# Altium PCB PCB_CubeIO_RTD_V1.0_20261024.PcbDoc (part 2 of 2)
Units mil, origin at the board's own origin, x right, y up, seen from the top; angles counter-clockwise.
Board outline 9739 x 8533 mil, 4 copper layers (TopLayer, GND, VCC, BottomLayer); 78 components, 50 nets, 272 pads, 89 vias.
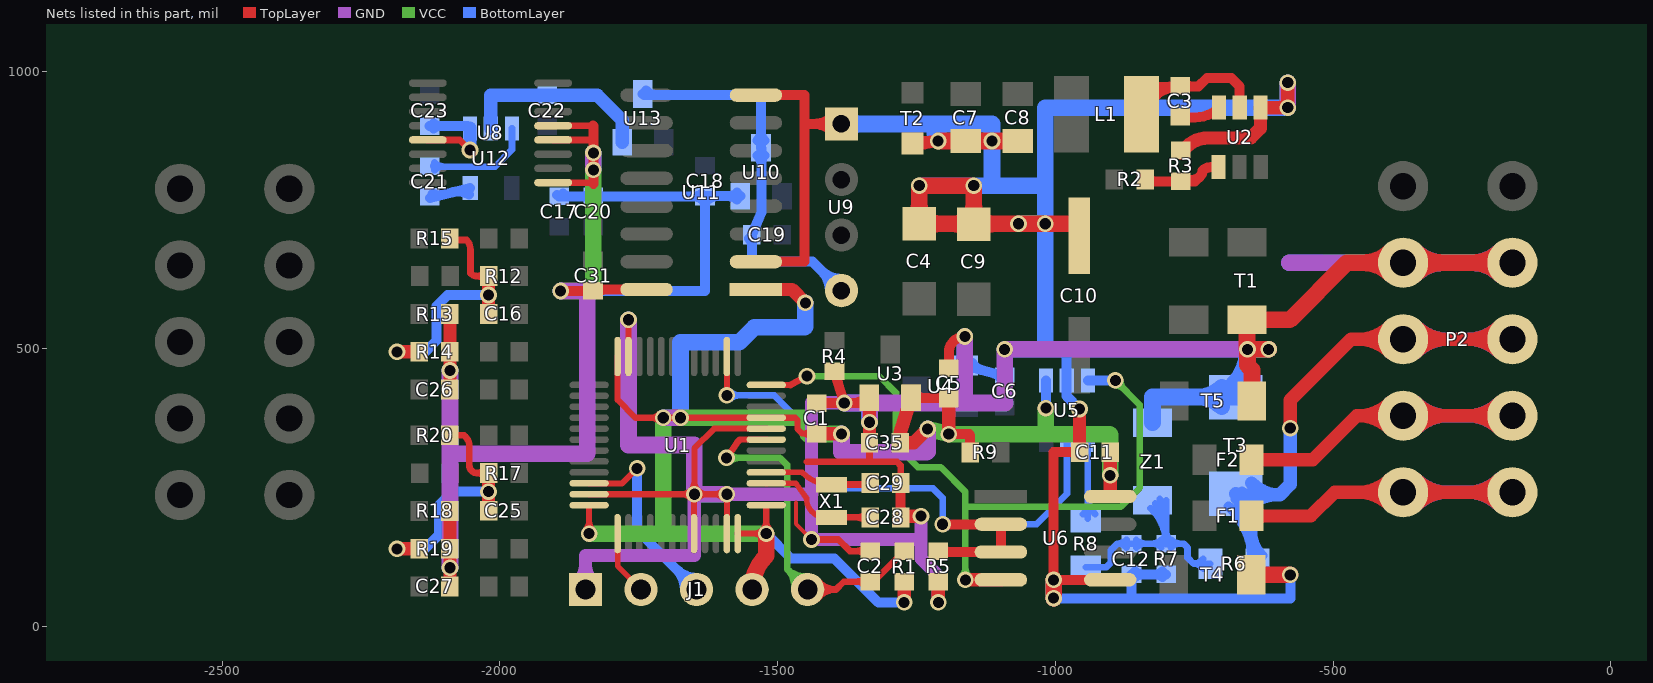
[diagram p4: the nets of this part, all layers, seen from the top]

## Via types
v1: diameter 30, hole 20, TopLayer to BottomLayer, 87 vias
v2: diameter 24, hole 12, TopLayer to BottomLayer, 2 vias

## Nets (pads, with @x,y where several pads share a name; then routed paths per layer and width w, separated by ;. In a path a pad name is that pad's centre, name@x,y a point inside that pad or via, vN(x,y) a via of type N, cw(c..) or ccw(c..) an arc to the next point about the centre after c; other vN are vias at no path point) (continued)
CPU_TXD: U1.12 U5.3 U6.4 | length 1451.7
  TopLayer w11: U1.12@-1520.51,435.14 -1476.96,435.14
  TopLayer w12: -1476.96,435.14 v1(-1446.96,450.87)
  TopLayer w24: v1(-1161.96,84.27) U6.4@-1097.96,84.27
  VCC w12: v1(-1446.96,450.87) -1316.96,450.87 -1286.96,420.87 -1286.96,326.68 -1247.16,286.87 -1206.16,286.87 -1161.96,242.68 -1161.96,215.87 ; v1(-1161.96,84.27) -1161.96,215.87 ; v1(-891.96,443.27) -847.96,399.27 -847.96,249.87 -881.96,215.87 -1161.96,215.87 ; -1161.96,106 cw(c-1183.69,106) -1168.32,90.64 ccw(c-1183.69,106) -1161.96,106 ; -1161.96,106 ccw(c-1140.23,106) -1155.6,90.64 cw(c-1140.23,106) -1161.96,106 ; -876.6,427.91 cw(c-861.23,443.27) -882.96,443.27 ccw(c-861.23,443.27) -876.6,427.91 ; -876.6,427.91 ccw(c-891.96,412.55) -891.96,434.27 cw(c-891.96,412.55) -876.6,427.91
  BottomLayer w18: U5.3@-941.16,443.27 v1(-891.96,443.27)
CPU_TXDEN: R5.2 U1.14 U5.5 U6.2 U6.3 | length 1412.1
  TopLayer w11: v1(-1591.38,416.46) U1.14@-1591.38,486.32
  TopLayer w18: R5.2@-1210.67,134.27 U6.3@-1097.96,134.27 U6.2@-1097.96,184.27 v1(-1202.96,184.27) ; R5.2@-1203.93,140.66 ccw(c-1188.5,156.09) -1188.5,134.27 cw(c-1188.5,156.09) R5.2@-1203.93,140.66
  BottomLayer w12: v1(-1591.38,416.46) -1506.54,416.46 -1444.96,354.87 -1444.96,273.87 -1419.96,248.87 -1219.96,248.87 -1202.96,231.87 v1(-1202.96,184.27) -1033.96,184.27 -978.96,239.27 U5.5@-978.96,336.27 ; -1569.65,416.46 cw(c-1569.65,438.18) -1585.01,422.82 ccw(c-1569.65,438.18) -1569.65,416.46 ; -1569.65,416.46 ccw(c-1569.65,394.73) -1585.01,410.09 cw(c-1569.65,394.73) -1569.65,416.46 ; -1181.23,184.27 cw(c-1181.23,206) -1196.6,190.64 ccw(c-1181.23,206) -1181.23,184.27 ; -1181.23,184.27 ccw(c-1181.23,162.55) -1196.6,177.91 cw(c-1181.23,162.55) -1181.23,184.27
DVDD: C1.1 C5.1 C11.2 C35.1 J1.4 R1.2 R9.2 U1.1 U1.9 U1.24 U1.36 U1.48 U3.2 U5.1 U6.8 U11.1 | length 4234.6
  TopLayer w11: v1(-1839.41,167.42) U1.36@-1839.41,218.6 ; U1.24@-1788.23,486.32 -1788.23,408.14 -1756.17,376.09 U1.9@-1520.51,376.09 -1468.17,376.09 -1463.96,371.87 -1463.96,355.75 -1455.58,347.38 ; U1.48@-1571.69,167.42 v1(-1520.51,167.42) ; v1@-1520.51,169.97 U1.1@-1520.51,218.6 ; C1.1@-1429.67,347.38 -1455.58,347.38 ; -1839.41,190.36 cw(c-1862.34,190.36) -1846.13,174.14 ccw(c-1862.34,190.36) -1839.41,190.36 ; -1839.41,190.36 ccw(c-1816.47,190.36) -1832.69,174.14 cw(c-1816.47,190.36) -1839.41,190.36 ; -1728.89,376.08 cw(c-1728.89,353.15) -1712.68,369.37 ccw(c-1728.89,353.15) -1728.89,376.08 ; -1728.89,376.09 ccw(c-1728.89,399.02) -1712.68,382.8 cw(c-1728.89,399.02) -1728.89,376.09 ; -1543.45,167.42 cw(c-1543.45,144.49) -1527.23,160.71 ccw(c-1543.45,144.49) -1543.45,167.42 ; -1543.45,167.42 ccw(c-1543.45,190.36) v1@-1527.23,174.14 ; -1543.45,167.42 ccw(c-1543.45,190.36) v1@-1527.23,174.14 ; v1@-1527.23,174.14 ccw(c-1543.45,190.36) -1520.51,190.36 ; v1@-1527.23,174.14 ccw(c-1543.45,190.36) -1520.51,190.36 ; -1520.51,190.36 ccw(c-1497.58,190.36) -1513.79,174.14 cw(c-1497.58,190.36) -1520.51,190.36 ; -1455.58,347.38 cw(c-1455.58,324.53) -1439.06,340.3 ccw(c-1455.58,324.53) -1455.58,347.38 ; -1455.58,347.38 ccw(c-1455.58,370.22) -1439.06,354.45 cw(c-1455.58,370.22) -1455.58,347.38
  TopLayer w18: U3.2@-1259.96,411.87 C5.1@-1198.77,411.87 ; v1(-1191.96,346.56) -1154.96,346.56 -1153.58,345.18 R9.2@-1153.58,313.56 ; U6.8@-901.34,234.51 U6.8@-901.11,234.27 ; -1238.92,411.87 cw(c-1238.92,432.92) -1253.8,418.04 ccw(c-1238.92,432.92) -1238.92,411.87 ; -1238.92,411.87 ccw(c-1238.92,390.83) -1253.8,405.71 cw(c-1238.92,390.83) -1238.92,411.87 ; -1153.58,331.82 cw(c-1169.86,331.82) -1158.35,320.3 ccw(c-1169.86,331.82) -1153.58,331.82 ; -1153.58,331.83 ccw(c-1137.28,331.83) -1148.8,320.3 cw(c-1137.28,331.83) -1153.58,331.83 ; -1213.59,411.87 cw(c-1213.59,390.41) -1198.41,405.59 ccw(c-1213.59,390.41) -1213.59,411.87
  TopLayer w24: U11.1@-1539,607 -1474,607 v1(-1450,583) ; C1.1@-1429.67,347.38 v1@-1385.46,347.38 ; C35.1@-1279.46,331.16 -1254.67,331.16 v1(-1229.96,355.87) ; C35.1@-1279.46,348.16 U3.2@-1259.96,411.87 ; v1(-1272.25,43.56) R1.2@-1272.25,80.66 ; v1(-1191.96,346.56) C5.1@-1191.96,410.85 ; U6.8@-901.34,234.51 C11.2@-901.34,313.98 ; U3.2@-1266.87,389.29 cw(c-1248.03,383.52) -1257.28,400.92 ccw(c-1248.03,383.52) U3.2@-1266.87,389.29
  TopLayer w30: J1.4@-1545.96,66.87 cw(c-1461.46,66.87) -1521.21,126.62 -1520.51,127.32 v1(-1520.51,167.42)
  GND w30: v1(-1705.96,376.09) v1(-1674.96,376.09) ; v1(-1384.96,346.87) -1384.96,313.87 -1231.27,313.87 -1229.96,315.18 v1(-1229.96,355.87)
  VCC w24: -902.25,346.56 -901.34,345.66
  VCC w30: v1(-1839.41,167.42) v1(-1520.51,167.42) ; -1705.96,168.42 v1(-1705.96,376.09) v1(-1674.96,376.09) -1445.96,376.09 -1445.96,347.38 -1445.96,346.87 v1(-1384.96,346.87) ; v1(-1229.96,355.87) v1(-1191.96,346.56) -902.25,346.56 ; -1016.96,351.56 v1(-1016.96,393.27) ; v1(-901.34,272.27) -901.34,345.66
  BottomLayer w18: v1(-1520.51,167.42) -1475.96,122.87 -1397.96,122.87 -1318.65,43.56 v1(-1272.25,43.56) ; v1(-1016.96,393.27) U5.1@-1016.96,443.27
  BottomLayer w30: v1(-1705.96,376.09) v1(-1674.96,376.09) -1674.96,512 -1569,512 -1542,539 -1451,539 -1450,540 v1(-1450,583)
GNDX: C1.2 C2.2 C4.2 C5.2 C6.2 C7.2 C8.2 C9.2 C10.2 C11.1 C12.2 C28.1 C29.1 C35.2 J1.1 P2.2 R3.1 R4.1 R5.1 R7.1 T1.2 T2.2 T3.2 T4.2 T5.2 U1.8 U1.23 U1.35 U1.44 U1.47 U2.4 U3.1 U4.1 U5.2 U6.5 U9.1 U11.2 U11.8 Z1.1 | length 15631
  TopLayer w8: -1466.96,222.87 -1466.96,184.87 v1(-1438.96,156.87)
  TopLayer w11: U1.35@-1839.41,238.29 -1591.79,238.29 v1@-1591.38,237.87 ; U1.23@-1768.54,486.32 v1(-1768.54,552.46) ; U1.44@-1650.43,167.42 v1@-1650.43,238.29 ; v1(-1649.96,238.29) -1649.96,320.87 -1614.43,356.4 U1.8@-1520.51,356.4 ; U1.47@-1591.38,167.42 v1(-1591.38,238.29) ; -1672.89,238.29 cw(c-1672.89,215.35) -1656.68,231.57 ccw(c-1672.89,215.35) -1672.89,238.29 ; -1672.89,238.29 ccw(c-1672.89,261.22) v1@-1656.68,245.01 ; -1672.89,238.29 ccw(c-1672.89,261.22) v1@-1656.68,245.01 ; v1@-1656.68,245.01 ccw(c-1672.89,261.22) -1649.96,261.22 ; v1@-1656.68,245.01 ccw(c-1672.89,261.22) -1649.96,261.22 ; -1649.96,261.22 ccw(c-1627.02,261.22) v1@-1643.24,245.01 ; -1649.96,261.22 ccw(c-1627.02,261.22) v1@-1643.24,245.01 ; v1@-1643.24,245.01 ccw(c-1627.02,261.22) -1627.02,238.29 ; v1@-1643.24,245.01 ccw(c-1627.02,261.22) -1627.02,238.29 ; -1627.02,238.29 ccw(c-1627.02,215.35) -1643.24,231.57 cw(c-1627.02,215.35) -1627.02,238.29 ; -1614.31,238.29 cw(c-1614.31,215.35) -1598.09,231.57 ccw(c-1614.31,215.35) -1614.31,238.29 ; -1614.31,238.29 ccw(c-1614.31,261.22) -1598.09,245.01 cw(c-1614.31,261.22) -1614.31,238.29
  TopLayer w12: -1446.96,296.87 -1284.96,296.87 -1278.46,290.38 C29.1@-1278.46,258.56 ; v1(-1438.96,156.87) -1390.96,156.87 -1369.98,135.9 C2.2@-1333.09,135.9 ccw(c-1333.09,136.99) C2.2@-1332,136.99 ; -1334.58,297.26 C35.2@-1334.58,331.16 ; -1358.59,135.9 cw(c-1358.59,112.36) -1341.95,129 ccw(c-1358.59,112.36) -1358.59,135.9 ; -1358.59,135.9 ccw(c-1358.59,159.43) -1341.95,142.79 cw(c-1358.59,159.43) -1358.59,135.9
  TopLayer w18: U11.2@-1539,657 -1452,657 -1452,957 U11.8@-1539,957 ; -1452,905 U9.1@-1385,905 ; C1.2@-1429.67,402.49 U3.1@-1334.58,402.49 ; R4.1@-1397.67,459.38 v1(-1379.96,402.49) ; C28.1@-1278.46,190.52 C28.1@-1278.46,196.56 -1278.46,228.87 C29.1@-1278.46,258.56 ; C5.2@-1191.67,465.47 -1191.67,493.56 ; C11.1@-956.46,313.98 -1003.25,313.98 -1003.25,85.56 -1001.96,84.27 -977.96,84.27 U6.5@-901.11,84.27 ; -1435.7,905 cw(c-1435.7,854.3) -1399.85,890.15 ccw(c-1435.7,854.3) -1435.7,905 ; -1435.7,905 ccw(c-1435.7,955.7) -1399.85,919.85 cw(c-1435.7,955.7) -1435.7,905 ; -1411.41,402.49 cw(c-1411.41,418.78) -1422.93,407.26 ccw(c-1411.41,418.78) -1411.41,402.49 ; -1411.41,402.49 ccw(c-1411.41,386.2) -1422.93,397.72 cw(c-1411.41,386.2) -1411.41,402.49 ; -1278.46,214.83 cw(c-1294.76,214.83) -1283.24,203.3 ccw(c-1294.76,214.83) -1278.46,214.83 ; -1278.46,214.82 ccw(c-1262.18,214.82) -1273.69,203.3 cw(c-1262.18,214.82) -1278.46,214.82 ; -1191.67,481.76 cw(c-1207.96,481.76) -1196.44,470.24 ccw(c-1207.96,481.76) -1191.67,481.76 ; -1191.67,481.76 ccw(c-1175.38,481.76) -1186.9,470.24 cw(c-1175.38,481.76) -1191.67,481.76 ; -1191.67,493.56 cw(c-1162.96,493.56) v1(-1162.96,522.27) ; -1191.67,493.56 cw(c-1162.96,493.56) v1(-1162.96,522.27) ; -1191.67,493.56 cw(c-1162.96,493.56) v1(-1162.96,522.27) ; -972.75,313.98 cw(c-972.75,297.69) -961.23,309.21 ccw(c-972.75,297.69) -972.75,313.98 ; -972.75,313.98 ccw(c-972.75,330.28) -961.23,318.76 cw(c-972.75,330.28) -972.75,313.98 ; -1391.31,438.94 cw(c-1369.63,445.68) -1389.73,456.24 ccw(c-1369.63,445.68) -1391.31,438.94 ; -1364.4,402.49 ccw(c-1364.4,435.41) -1341.12,412.13 cw(c-1364.4,435.41) -1364.4,402.49 ; C29.1@-1283.24,251.82 cw(c-1294.76,240.3) -1278.46,240.3 ccw(c-1294.76,240.3) C29.1@-1283.24,251.82 ; -1278.46,240.31 cw(c-1262.18,240.31) -1273.69,251.82 ccw(c-1262.18,240.31) -1278.46,240.31 ; -1003.25,99.46 ccw(c-987.77,99.46) -998.72,88.52 cw(c-987.77,99.46) -1003.25,99.46
  TopLayer w24: C35.2@-1334.58,334.16 U3.1@-1334.58,411.49 ; C28.1@-1278.46,198.87 v1(-1241.96,198.87) ; T2.2@-1257,868.76 v1(-1210.96,874.23) ; v1(-1210.67,43.56) R5.1@-1210.67,80.78 ; C11.1@-956.46,313.98 v1(-956.46,391.78) ; R3.1@-774.25,853.37 -763.86,863.76 cw(c-724.96,824.86) -724.96,879.87 -647.91,879.87 -630.69,897.09 U2.4@-630.69,934.49 ; U2.4@-630.96,934.49 U2.4@-630.69,934.49 ; v1(-581.51,979.49) v1(-581.51,934.49) ; v1@-581,935 v1(-581.51,934.49) ; U2.4@-630.69,934.49 v1(-581.51,934.49) ; T2.2@-1252.24,875.8 ccw(c-1238.66,893.04) -1236.08,871.25 cw(c-1238.66,893.04) T2.2@-1252.24,875.8
  TopLayer w30: v1(-1245,794) v1@-1244.96,793.96 ; v1(-1210.96,874.23) C7.2@-1160.96,874.23 C8.2@-1067.96,874.23 ; C9.2@-1146.96,724.27 v1(-1146.96,794.04) -1147.04,793.96 v1@-1244.96,793.96 ; v1(-1002.96,51.27) v1(-1002.96,84.27) ; C10.2@-959.96,725.27 C4.2@-1244.96,725.27 v1@-1244.96,793.96 ; v1@-654.96,500.27 T1.2@-654.96,552.27 -577.73,552.27 -474.8,655.2 P2.2@-177,655.2 ; T4.2@-646.96,93.27 v1(-576.96,93.27) ; T5.2@-645.96,406.27 -645.96,462.27 -653.96,470.27 v1(-653.96,499.27) v1(-615.96,499.27) ; -1244.96,761.49 cw(c-1281.17,761.49) -1255.57,735.88 ccw(c-1281.17,761.49) -1244.96,761.49 ; -1244.96,761.49 ccw(c-1208.75,761.49) C4.2@-1234.35,735.88 ; -1244.96,761.49 ccw(c-1208.75,761.49) C4.2@-1234.35,735.88 ; C4.2@-1234.35,735.88 ccw(c-1208.75,761.49) -1208.75,725.27 ; C4.2@-1234.35,735.88 ccw(c-1208.75,761.49) -1208.75,725.27 ; -1208.75,725.27 ccw(c-1208.75,689.06) -1234.35,714.67 cw(c-1208.75,689.06) -1208.75,725.27 ; C9.2@-1157.57,734.88 cw(c-1180.76,758.07) -1180.76,725.27 ccw(c-1180.76,758.07) C9.2@-1157.57,734.88 ; C9.2@-1157.57,734.88 ccw(c-1183.17,760.49) -1146.96,760.49 ; C9.2@-1157.57,734.88 ccw(c-1183.17,760.49) -1146.96,760.49 ; -1146.96,760.49 ccw(c-1110.75,760.49) C9.2@-1136.35,734.88 ; -1146.96,760.49 ccw(c-1110.75,760.49) C9.2@-1136.35,734.88 ; C9.2@-1136.35,734.88 ccw(c-1113.16,758.07) -1113.16,725.27 cw(c-1113.16,758.07) C9.2@-1136.35,734.88 ; -446.94,655.2 cw(c-446.94,582.11) -395.26,633.8 ccw(c-446.94,582.11) -446.94,655.2 ; -446.94,655.2 ccw(c-446.94,728.3) -395.26,676.61 cw(c-446.94,728.3) -446.94,655.2 ; -300.76,655.2 cw(c-300.76,728.3) -352.44,676.61 ccw(c-300.76,728.3) -300.76,655.2 ; -300.76,655.2 ccw(c-300.76,582.11) -352.44,633.8 cw(c-300.76,582.11) -300.76,655.2 ; -250.09,655.2 cw(c-250.09,582.11) -198.41,633.8 ccw(c-250.09,582.11) -250.09,655.2 ; -250.09,655.2 ccw(c-250.09,728.3) -198.41,676.61 cw(c-250.09,728.3) -250.09,655.2 ; -1185.59,725.27 cw(c-1185.59,685.65) -1157.57,713.67 ccw(c-1185.59,685.65) -1185.59,725.27 ; C9.2@-1136.35,713.67 cw(c-1108.33,685.65) -1108.33,725.27 ccw(c-1108.33,685.65) C9.2@-1136.35,713.67
  GND w24: J1.1@-1845.96,66.87 -1845.96,127.96 -1846,128 -1650,128 -1649.96,128.04 v1(-1649.96,238.29) ; v1(-1591.38,238.29) -1438.38,238.29 ; v1(-1379.96,402.49) -1380.47,403 -1439,403 -1438.96,402.96 v1(-1438.96,156.87) -1241.96,156.87 ; v1(-1241.96,198.87) -1241.96,122.87 -1210.67,91.58 v1(-1210.67,43.56) ; -1845.96,110.33 cw(c-1889.42,110.33) -1858.69,79.6 ccw(c-1889.42,110.33) -1845.96,110.33 ; -1845.96,110.33 ccw(c-1802.5,110.33) -1833.23,79.6 cw(c-1802.5,110.33) -1845.96,110.33
  GND w30: J1.1@-1846.96,67.87 J1.1@-1845.96,66.87 ; v1(-1768.54,552.46) -1768.54,327.46 -1768.35,327 -1650.09,327 -1649.96,326.87 v1(-1649.96,238.29) v1(-1591.38,238.29) ; v1(-1379.96,402.49) -1090.58,402.49 ; v1(-1334.58,367.87) -1333.96,368.49 -1333.96,402.49 ; -1162.96,407.49 v1(-1162.96,522.27) ; -1091.25,403.16 v1(-1091.25,499.27) v1(-615.96,499.27) ; v1(-1066.16,725.27) v1(-1018.16,725.27) ; v1(-1002.96,51.27) v1(-1002.96,84.27) ; v1(-581.51,934.49) v1(-581.51,979.49) ; -578.52,655.2 P2.2@-177,655.2
  VCC w30: v1(-1649.96,238.29) v1(-1591.38,238.29) ; v1(-1066.16,725.27) v1(-1018.16,725.27) ; v1(-1002.96,51.27) v1(-1002.96,84.27) ; v1(-653.96,499.27) v1(-615.96,499.27) ; v1(-581.51,934.49) v1(-581.51,979.49) ; -515,655.2 P2.2@-177,655.2
  BottomLayer w18: U4.1@-1162.96,470.27 C6.2@-1091.25,450.89 ; v1(-1002.96,84.27) v1(-1002.96,51.27) -1001.96,50.27 -873.96,50.27 ; -979.67,499.27 -979.67,443.39 U5.2@-979.56,443.27 -979.56,414.88 v1(-956.46,391.78) ; R7.1@-800.66,94.16 C12.2@-862.96,94.16 -862.96,50.27 -873.96,50.27 ; v1(-576.96,93.27) -576.36,92.68 -576.36,50.27 -873.96,50.27 ; -862.96,77.87 cw(c-846.67,77.87) -858.19,89.39 ccw(c-846.67,77.87) -862.96,77.87 ; -862.96,77.87 ccw(c-879.25,77.87) -867.73,89.39 cw(c-879.25,77.87) -862.96,77.87 ; -844.7,94.16 cw(c-844.7,110.45) -856.22,98.93 ccw(c-844.7,110.45) -844.7,94.16 ; -844.7,94.16 ccw(c-844.7,77.87) -856.22,89.39 cw(c-844.7,77.87) -844.7,94.16 ; U4.1@-1149.5,474.62 ccw(c-1126.69,487.72) -1133.55,462.32 cw(c-1126.69,487.72) U4.1@-1149.5,474.62 ; -1110.01,455.96 cw(c-1114.72,438.54) -1099.07,447.53 ccw(c-1114.72,438.54) -1110.01,455.96 ; v1@-998.72,55.52 ccw(c-986.06,68.17) -986.06,50.27 cw(c-986.06,68.17) v1@-998.72,55.52 ; -819.09,94.16 ccw(c-819.09,110.86) -807.28,99.05 cw(c-819.09,110.86) -819.09,94.16 ; -818.51,94.16 cw(c-818.51,78.28) -807.28,89.51 ccw(c-818.51,78.28) -818.51,94.16 ; v1@-581.2,89.03 cw(c-592.89,77.34) -576.36,77.34 ccw(c-592.89,77.34) v1@-581.2,89.03
  BottomLayer w24: C6.2@-1091.25,450.89 v1(-1091.25,499.27)
  BottomLayer w30: v1(-1649.96,238.29) v1(-1591.38,238.29) ; U9.1@-1385,905 -1114,905 -1113.96,904.96 v1(-1113.96,874.23) -1113.96,795.04 -1115,794 ; v1(-1379.96,402.49) -1335.19,402.49 -1334.58,401.87 v1(-1334.58,367.87) ; v1(-1245,794) -1019,794 -1018.16,793.16 -1018.16,774 ; U4.1@-1162.96,470.27 v1(-1162.96,522.27) ; v1(-1091.25,499.27) v1(-615.96,499.27) ; v1(-1066.16,725.27) v1(-1018.16,725.27) ; -1018.16,501.27 v1(-1018.16,725.27) ; v1(-1002.96,51.27) v1(-1002.96,84.27) ; Z1.1@-824.96,367.27 -824.96,413.27 T3.2@-674.96,413.27 ; T3.2@-653.96,434.27 v1(-653.96,499.27) ; v1(-581.51,979.49) v1(-581.51,934.49) -1018.16,934.49 -1018.16,774 ; -578.52,655.2 P2.2@-177,655.2 P2.2@-373.85,655.2 ; P2.2@-352.44,633.8 cw(c-300.76,582.11) -300.76,655.2 cw(c-300.76,728.3) P2.2@-352.44,676.61 ; P2.2@-198.41,633.8 ccw(c-250.09,582.11) -250.09,655.2 ccw(c-250.09,728.3) P2.2@-198.41,676.61 ; -1348.79,905 cw(c-1348.79,941.21) -1374.39,915.61 ccw(c-1348.79,941.21) -1348.79,905 ; -1348.79,905 ccw(c-1348.79,868.79) -1374.39,894.39 cw(c-1348.79,868.79) -1348.79,905 ; v1(-1210.96,874.23) cw(c-1194.1,889.1) -1210,905 ; v1(-1210.96,874.23) cw(c-1194.1,889.1) -1210,905 ; v1(-1210.96,874.23) -1210.96,904.04 -1210,905 ; v1(-1018.16,725.27) -1018.16,774 ; -743.31,413.27 cw(c-743.31,352.92) -700.64,395.6 ccw(c-743.31,352.92) -743.31,413.27 ; -743.31,413.27 ccw(c-743.31,473.63) -700.64,430.95 cw(c-743.31,473.63) -743.31,413.27 ; v1(-653.96,499.27) cw(c-745.26,499.27) -683.79,431.76 ccw(c-745.26,499.27) v1(-653.96,499.27)
ISO+2V0: C22.2 U12.2 U13.2 | length 354.4
  BottomLayer w24: U12.2@-2016.6,897 -2016.6,956.38 ; -2016.54,956.41 -1824.41,956.41 -1780,912 U13.2@-1780,872
ISO+3V3: C17.1 C18.2 C20.1 C26.2 C27.2 C31.2 R13.1 R14.1 R18.1 R19.1 U8.9 U8.12 U8.13 U10.2 U11.16 | length 3295.8
  TopLayer w12: U8.9@-1904.17,799.43 -1834.14,799.43 -1831.71,797 ; U8.12@-1904.17,876.2 -1833.91,876.2 -1831.71,874 ; U8.13@-1904.17,901.79 -1832.21,901.79 -1832,902
  TopLayer w18: C27.2@-2089.95,72.3 C27.2@-2089.89,72.24 ; C26.2@-2089.89,426.79 C26.2@-2089.89,426.79 ; v1(-1890.62,604.38) C31.2@-1832.29,604.38 -1829.67,607 U11.16@-1736,607 ; -1832,902 -1831.71,901.71 v1(-1831.71,822.29) -1831.71,797 ; -1850.55,604.38 cw(c-1850.55,588.09) -1839.03,599.61 ccw(c-1850.55,588.09) -1850.55,604.38 ; -1850.55,604.38 ccw(c-1850.55,620.67) -1839.03,609.15 cw(c-1850.55,620.67) -1850.55,604.38 ; C31.2@-1825.55,599.61 cw(c-1807.71,581.77) -1807.71,607 ccw(c-1807.71,581.77) C31.2@-1825.55,599.61
  TopLayer w24: C27.2@-2089.95,72.3 R18.1@-2089.95,208.16 ; C26.2@-2089.89,426.79 R13.1@-2089.95,562.71
  GND w30: v1(-2089.95,106) -2089.95,311 ; v1(-2089.95,461) -2089.95,311 ; v1(-1890.62,604.38) -1843,604.38 -1843,311 -2089.95,311 ; v1(-1831.71,822.29) v1(-1831.71,853)
  VCC w30: v1(-1890.62,604.38) -1833,604.38 -1831.71,605.67 v1(-1831.71,853)
  BottomLayer w18: C17.1@-1896.83,777.5 -1893.72,774.38 C18.2@-1630.71,774.38 ; v1(-1890.62,604.38) -1630.71,604.38 C18.2@-1630.71,774.38 ; C20.1@-1831.71,774.88 v1(-1831.71,822.29) ; U10.2@-1567,775 -1630.09,775 C18.2@-1630.71,774.38 ; -1831.71,791.17 cw(c-1848,791.17) -1836.48,779.65 ccw(c-1848,791.17) -1831.71,791.17 ; -1831.71,791.17 ccw(c-1815.42,791.17) -1826.94,779.65 cw(c-1815.42,791.17) -1831.71,791.17 ; -1648.97,774.38 cw(c-1648.97,758.09) -1637.45,769.61 ccw(c-1648.97,758.09) -1648.97,774.38 ; -1648.97,774.38 ccw(c-1648.97,790.67) -1637.45,779.15 cw(c-1648.97,790.67) -1648.97,774.38 ; -1630.71,758.09 cw(c-1614.42,758.09) -1625.94,769.61 ccw(c-1614.42,758.09) -1630.71,758.09 ; -1630.71,758.09 ccw(c-1647,758.09) -1635.48,769.61 cw(c-1647,758.09) -1630.71,758.09 ; -1588.04,775 cw(c-1588.04,753.96) -1573.16,768.84 ccw(c-1588.04,753.96) -1588.04,775 ; -1588.04,775 ccw(c-1588.04,796.04) -1573.16,781.16 cw(c-1588.04,796.04) -1588.04,775 ; C17.1@-1886.69,779.65 ccw(c-1873.97,792.37) -1873.97,774.38 cw(c-1873.97,792.37) C17.1@-1886.69,779.65 ; -1851.17,774.38 ccw(c-1851.17,792.37) -1838.45,779.65 cw(c-1851.17,792.37) -1851.17,774.38 ; C20.1@-1824.97,779.65 ccw(c-1812.25,792.37) -1812.25,774.38 cw(c-1812.25,792.37) C20.1@-1824.97,779.65 ; C18.2@-1623.97,769.61 cw(c-1610.96,756.6) -1610.96,775 ccw(c-1610.96,756.6) C18.2@-1623.97,769.61
  BottomLayer w30: v1(-1831.71,822.29) v1(-1831.71,853)
ISO+3V6: C19.1 U9.4 U10.3 U13.3 | length 1064.1
  BottomLayer w18: U13.3@-1743,959 -1741,957 -1530,957 U10.3@-1530,862 -1529,861 -1529,746 C19.1@-1546.5,705.29 -1546,704.79 -1546,657 -1437,657 U9.4@-1385,605 ; -1530,890.33 cw(c-1551.04,890.33) -1536.16,875.45 ccw(c-1551.04,890.33) -1530,890.33 ; -1530,890.33 ccw(c-1508.96,890.33) -1523.84,875.45 cw(c-1508.96,890.33) -1530,890.33 ; -1420.85,640.85 cw(c-1456.7,605) -1406,605 ccw(c-1456.7,605) -1420.85,640.85 ; -1420.85,640.85 ccw(c-1385,676.7) -1385,626 cw(c-1385,676.7) -1420.85,640.85 ; U13.3@-1736.84,965.16 ccw(c-1717.13,984.87) -1717.13,957 cw(c-1717.13,984.87) U13.3@-1736.84,965.16 ; C19.1@-1551.27,698.55 cw(c-1564,685.82) -1546,685.82 ccw(c-1564,685.82) C19.1@-1551.27,698.55 ; U10.3@-1536.16,848.55 cw(c-1553.46,831.26) -1529,831.26 ccw(c-1553.46,831.26) U10.3@-1536.16,848.55 ; -1529,836.09 cw(c-1511.37,836.09) -1523.84,848.55 ccw(c-1511.37,836.09) -1529,836.09
ISO-2V0: C23.2 U8.5 U12.1 | length 247.7
  TopLayer w12: U8.5@-2129.82,876.2 -2072.2,876.2 v1(-2054,858)
  BottomLayer w18: C23.2@-2126.46,901.18 -2058.18,901.18 U12.1@-2054,897 ; -2108.2,901.18 cw(c-2108.2,917.47) -2119.72,905.95 ccw(c-2108.2,917.47) -2108.2,901.18 ; -2108.2,901.18 ccw(c-2108.2,884.89) -2119.72,896.41 cw(c-2108.2,884.89) -2108.2,901.18
  BottomLayer w24: v1(-2054,858) U12.1@-2054,897
NetC3_1: C3.1 L1.1 U2.5 | length 517.6
  TopLayer w18: L1.1@-864.17,971.77 C3.1@-779.25,971.77 ; C3.1@-758.16,972.87 -742.15,972.87 -727.16,987.87 -683.16,987.87 -667.96,972.68 U2.5@-667.96,934.27 ; -753.24,972.87 -776.59,972.87 ccw(c-776.59,969.11) C3.1@-779.25,971.77 ; C3.1@-779.25,971.77 ccw(c-779.25,913.75) -826.61,947.28 cw(c-779.25,913.75) C3.1@-779.25,971.77 ; C3.1@-768.14,978.14 ccw(c-755.42,990.86) -755.42,972.87 ; C3.1@-768.14,978.14 ccw(c-755.42,990.86) -755.42,972.87 ; C3.1@-768.14,978.14 ccw(c-755.42,990.86) -755.42,972.87 ; C3.1@-768.14,978.14 ccw(c-755.42,990.86) -755.42,972.87 ; L1.1@-841.3,957.68 cw(c-814.05,938.38) -814.05,971.77 ccw(c-814.05,938.38) L1.1@-841.3,957.68 ; -797,971.77 ccw(c-797,993.53) -781.62,978.14 cw(c-797,993.53) -797,971.77
NetC3_2: C3.2 U2.6 | length 126.3
  TopLayer w18: C3.2@-779.25,916.66 -748.54,916.66 ; -748.54,916.66 ccw(c-748.54,977.53) U2.6@-705.49,934.49 cw(c-748.54,977.53) -748.54,916.66
NetC12_1: C12.1 R6.1 R7.2 R8.2 Z1.2 | length 1115.4
  BottomLayer w12: R8.2@-944.96,106.63 -908.61,106.63 -899.96,115.27 -899.96,137.69 -888.25,149.39 ; Z1.2@-800.54,227.27 R7.2@-800.54,149.39 ; R6.1@-720.96,113.27 -750.96,113.27 ; -888.25,149.39 cw(c-888.25,126.66) -871.93,142.49 ccw(c-888.25,126.66) -888.25,149.39 ; -888.25,149.39 R7.2@-800.54,149.39 ; -826.04,149.39 cw(c-826.04,125.86) -809.4,142.5 ccw(c-826.04,125.86) -826.04,149.39 ; -826.04,149.39 ccw(c-826.04,172.93) -809.4,156.29 cw(c-826.04,172.93) -826.04,149.39 ; R7.2@-800.54,149.39 -769.08,149.39 -761.96,142.27 -761.96,124.27 -750.96,113.27 ; -800.54,172.93 cw(c-824.07,172.93) -807.43,156.29 ccw(c-824.07,172.93) -800.54,172.93 ; -800.54,172.93 ccw(c-777.01,172.93) -793.65,156.29 cw(c-777.01,172.93) -800.54,172.93 ; -775.04,149.39 cw(c-775.04,172.93) -791.68,156.29 ccw(c-775.04,172.93) -775.04,149.39 ; -775.04,149.39 ccw(c-775.04,125.86) -791.68,142.5 cw(c-775.04,125.86) -775.04,149.39 ; -750.96,113.27 cw(c-750.96,92.36) -733.8,104.32 ccw(c-750.96,92.36) -750.96,113.27 ; -750.96,113.27 ccw(c-750.96,134.19) -733.8,122.23 cw(c-750.96,134.19) -750.96,113.27 ; -888.18,149.39 ccw(c-888.18,172.52) -871.82,156.17 cw(c-888.18,172.52) -888.18,149.39 ; C12.1@-854.1,142.38 cw(c-837.17,125.45) -837.17,149.39 ccw(c-837.17,125.45) C12.1@-854.1,142.38 ; C12.1@-854.1,156.17 ccw(c-837.75,172.52) -837.75,149.39 cw(c-837.75,172.52) C12.1@-854.1,156.17 ; Z1.2@-828.56,213.03 cw(c-889.89,148.05) -800.54,148.05 ccw(c-889.89,148.05) Z1.2@-828.56,213.03 ; Z1.2@-820.33,221.75 cw(c-863.63,175.87) -800.54,175.87 ccw(c-863.63,175.87) Z1.2@-820.33,221.75 ; Z1.2@-812.09,230.48 cw(c-837.37,203.7) -800.54,203.7 ccw(c-837.37,203.7) Z1.2@-812.09,230.48
NetC16_1: C16.1 R12.1 R14.2 R15.1 | length 540.1
  TopLayer w12: R15.1@-2089.95,698.93 ccw(c-2082.88,705.99) -2082.88,696 -2060,696 cw(c-2076.9,679.1) -2053,679.1 -2053,670.34 -2053,636 ccw(c-2041.21,647.79) -2041.21,631.11 ; R12.1@-2020.5,631.11 -2041.21,631.11 ; -2041.21,631.11 cw(c-2041.21,613.99) -2028.01,624.9 ccw(c-2041.21,613.99) -2041.21,631.11 ; -2041.21,631.11 ccw(c-2041.21,648.24) -2028.01,637.33 cw(c-2041.21,648.24) -2041.21,631.11
  TopLayer w18: R12.1@-2022.14,631.11 R12.1@-2020.5,631.11
  TopLayer w24: v1(-2185.23,494.6) R14.2@-2145.06,494.6 ; C16.1@-2020.5,563.01 R12.1@-2020.5,631.11
  BottomLayer w18: v1(-2185.23,494.6) -2134.4,494.6 -2114,515 -2114,577 -2094,597 v1(-2020.5,597)
NetC21_1: C21.1 U12.5 | length 170.2
  BottomLayer w18: C21.1@-2126.16,771.89 U12.5@-2053.54,789.79 U12.5@-2056.24,787.08 ; C21.1@-2121.12,779.36 ccw(c-2110.45,797.01) -2105.52,776.98 cw(c-2110.45,797.01) C21.1@-2121.12,779.36 ; -2084.49,782.16 cw(c-2075.48,745.61) -2056.01,777.82 ccw(c-2075.48,745.61) -2084.49,782.16
NetC21_2: C21.2 U12.3 | length 264.5
  BottomLayer w12: C21.2@-2116.1,828 -2009,828 -1978.2,858.8 U12.3@-1978.2,897 ; C21.2@-2117.72,821.8 cw(c-2102.75,806.84) -2102.75,828 ccw(c-2102.75,806.84) C21.2@-2117.72,821.8 ; C21.2@-2117.72,835.59 ccw(c-2099.4,853.91) -2099.4,828 cw(c-2099.4,853.91) C21.2@-2117.72,835.59
  BottomLayer w18: C21.2@-2117.29,829.19 C21.2@-2116.1,828
NetC25_1: C25.1 R17.1 R19.2 R20.1 | length 535.3
  TopLayer w12: R20.1@-2089.95,344.38 -2064.38,344.38 -2062.07,342.07 cw(c-2079.14,325) -2055,325 -2055,290 ccw(c-2041.57,290) -2041.57,276.57 ; R17.1@-2020.5,276.57 -2041.57,276.57 ; -2041.57,276.57 cw(c-2041.57,258.67) -2027.93,270.26 ccw(c-2041.57,258.67) -2041.57,276.57 ; -2041.57,276.57 ccw(c-2041.57,294.46) -2027.93,282.88 cw(c-2041.57,294.46) -2041.57,276.57
  TopLayer w18: R20.1@-2089.95,344.38 R20.1@-2088.31,344.38
  TopLayer w24: v1(-2185.23,140.05) R19.2@-2145.06,140.05 ; C25.1@-2020.5,208.46 R17.1@-2020.5,276.57
  BottomLayer w18: v1(-2185.23,140.05) -2134.95,140.05 -2110,165 -2110,218 -2085,243 v1(-2020.5,243)
NetC28_2: C28.2 U1.3 X1.2 | length 303.4
  TopLayer w10: U1.3@-1519.73,257.2 U1.3@-1520.51,257.97 -1467.49,257.97 -1465.3,255.78 -1447.96,230.87 ccw(c-1413.43,230.87) -1413.43,196.34 X1.2@-1402.96,196.34
  TopLayer w12: X1.2@-1410.96,196.74 C28.2@-1333.76,196.74 ; -1357.54,196.74 cw(c-1357.54,172.6) -1340.47,189.67 ccw(c-1357.54,172.6) -1357.54,196.74 ; -1356.68,196.74 ccw(c-1356.68,219.67) -1340.47,203.46 cw(c-1356.68,219.67) -1356.68,196.74
NetC29_2: C29.2 U1.4 X1.1 | length 202.1
  TopLayer w10: U1.4@-1520.51,277.66 -1455.96,277.66 -1455.44,277.14 ccw(c-1402.96,329.62) X1.1@-1402.96,255.4
  TopLayer w12: X1.1@-1410.96,255.81 -1336.34,255.81 C29.2@-1333.58,258.56
NetR2_1: R2.1 R3.2 U2.1 | length 308.7
  TopLayer w18: R2.1@-838.46,801.16 -748.84,801.16 -739.08,810.92 ; U2.1@-705.96,827.27 -719.5,827.27 ccw(c-719.5,805.42) -734.96,820.87 cw(c-749.04,820.87) -739.08,810.92 ; -739.08,810.92 cw(c-755.69,827.52) -768.57,807.9 ccw(c-755.69,827.52) -739.08,810.92 ; R2.1@-833.69,807.96 ccw(c-817.27,824.39) -817.27,801.16 cw(c-817.27,824.39) R2.1@-833.69,807.96 ; -795.15,801.16 ccw(c-795.15,821.19) -780.99,807.03 cw(c-795.15,821.19) -795.15,801.16 ; R3.2@-767.51,807.03 ccw(c-753.35,821.19) -753.35,801.16 cw(c-753.35,821.19) R3.2@-767.51,807.03
NetR8_1: R8.1 U5.4 | length 260.2
  BottomLayer w12: R8.1@-941.69,194.54 U5.4@-941.69,336.06 ; R8.1@-950.12,202.34 ccw(c-970.48,222.7) -941.69,222.7 cw(c-970.48,222.7) R8.1@-950.12,202.34 ; -941.69,235.43 ccw(c-894.9,235.43) -927.99,202.34 cw(c-894.9,235.43) -941.69,235.43
NRST: C2.1 J1.5 R1.1 U1.7 | length 1055.6
  TopLayer w11: -1567.96,336.71 U1.7@-1520.51,336.71
  TopLayer w12: v1(-1591.96,303.87) -1572.96,331.71 -1567.96,336.71 ; J1.5@-1445.96,66.87 -1394.96,66.87 ; R1.1@-1272.25,135.77 -1327.24,80.78 C2.1@-1333.09,80.78 -1381.05,80.78 -1394.96,66.87 ; -1394.96,66.87 cw(c-1394.96,109.06) -1427.47,82.17 ccw(c-1394.96,109.06) -1394.96,66.87 ; -1394.96,66.87 ccw(c-1394.96,24.69) -1427.47,51.58 cw(c-1394.96,24.69) -1394.96,66.87 ; -1358.6,80.78 cw(c-1358.6,57.25) -1341.95,73.89 ccw(c-1358.6,57.25) -1358.6,80.78 ; -1358.6,80.78 ccw(c-1358.6,104.32) -1341.95,87.68 cw(c-1358.6,104.32) -1358.6,80.78
  VCC w12: v1(-1591.96,303.87) -1495.96,303.87 -1482.96,290.87 -1482.96,103.87 ; v1@-1585.6,297.51 cw(c-1570.23,282.14) -1570.23,303.87 cw(c-1570.23,325.6) v1@-1585.6,310.24 ; J1.5@-1445.96,66.87 -1482.96,103.87 ; -1482.96,103.87 cw(c-1514.8,72.03) -1469.89,68.66 ccw(c-1514.8,72.03) -1482.96,103.87 ; -1482.96,103.87 ccw(c-1451.11,135.71) -1447.75,90.81 cw(c-1451.11,135.71) -1482.96,103.87
SDI12: P2.3 R6.2 T3.1 | length 2826.6
  TopLayer w24: v1(-576.96,357.27) -576.96,408.04 -467.59,517.41 P2.3@-177,517.41 ; -454.18,517.41 cw(c-454.18,437.08) -397.38,493.88 ccw(c-454.18,437.08) -454.18,517.41 ; -454.18,517.41 ccw(c-454.18,597.74) -397.38,540.94 cw(c-454.18,597.74) -454.18,517.41 ; -293.52,517.41 cw(c-293.52,597.74) -350.32,540.94 ccw(c-293.52,597.74) -293.52,517.41 ; -293.52,517.41 ccw(c-293.52,437.08) -350.32,493.88 cw(c-293.52,437.08) -293.52,517.41 ; -257.33,517.41 cw(c-257.33,437.08) -200.53,493.88 ccw(c-257.33,437.08) -257.33,517.41 ; -257.33,517.41 ccw(c-257.33,597.74) -200.53,540.94 cw(c-257.33,597.74) -257.33,517.41
  BottomLayer w18: T3.1@-670.96,235.27 T3.1@-674.96,239.27 -645.16,209.47 -645.16,122.12 R6.2@-636.31,113.27 ; T3.1@-687.78,216.31 cw(c-775.02,120.11) -645.16,120.11 ccw(c-775.02,120.11) T3.1@-687.78,216.31 ; T3.1@-675.69,229.64 cw(c-738.18,160.73) -645.16,160.73 ccw(c-738.18,160.73) T3.1@-675.69,229.64 ; T3.1@-663.6,242.98 cw(c-701.35,201.35) -645.16,201.35 ccw(c-701.35,201.35) T3.1@-663.6,242.98 ; -645.16,171.08 ccw(c-584.42,171.08) -627.37,128.13 cw(c-584.42,171.08) -645.16,171.08
  BottomLayer w24: T3.1@-674.96,239.27 -672.69,237 -595.96,237 ; v1(-576.96,357.27) -576.96,256 -595.96,237 ; P2.3@-373.85,517.41 P2.3@-177,517.41 ; P2.3@-350.32,493.88 cw(c-293.52,437.08) -293.52,517.41 cw(c-293.52,597.74) P2.3@-350.32,540.94 ; P2.3@-200.53,493.88 ccw(c-257.33,437.08) -257.33,517.41 ccw(c-257.33,597.74) P2.3@-200.53,540.94 ; -595.96,237 cw(c-595.96,307.39) -646.75,258.66 ccw(c-595.96,307.39) -595.96,237 ; T3.1@-647.16,219.47 cw(c-604.85,177.17) -604.85,237 ccw(c-604.85,177.17) T3.1@-647.16,219.47
SWCLK: J1.2 U1.37 | length 118.1
  TopLayer w10: U1.37@-1788.23,167.42 -1788.23,109.14 J1.2@-1745.96,66.87
SWDIO: J1.3 U1.34 | length 519.2
  TopLayer w11: U1.34@-1839.41,257.97 -1779.86,257.97 v1(-1752.96,284.87)
  BottomLayer w18: v1(-1752.96,284.87) -1752.96,173.87 J1.3@-1645.96,66.87 ; -1681.81,102.72 cw(c-1717.66,66.87) -1666.96,66.87 ccw(c-1717.66,66.87) -1681.81,102.72 ; -1681.81,102.72 ccw(c-1645.96,138.57) -1645.96,87.87 cw(c-1645.96,138.57) -1681.81,102.72
T+: F1.1 P2.5 | length 1767.2
  TopLayer w24: F1.1@-646.96,199.27 -539.73,199.27 -497.18,241.82 P2.5@-177,241.82 ; -623.65,199.27 cw(c-623.65,222.58) -640.13,206.1 ccw(c-623.65,222.58) -623.65,199.27 ; -623.65,199.27 ccw(c-623.65,175.97) -640.13,192.45 cw(c-623.65,175.97) -623.65,199.27 ; -454.18,241.82 cw(c-454.18,161.48) -397.38,218.29 ccw(c-454.18,161.48) -454.18,241.82 ; -454.18,241.82 ccw(c-454.18,322.15) -397.38,265.35 cw(c-454.18,322.15) -454.18,241.82 ; -293.52,241.82 cw(c-293.52,322.15) -350.32,265.35 ccw(c-293.52,322.15) -293.52,241.82 ; -293.52,241.82 ccw(c-293.52,161.48) -350.32,218.29 cw(c-293.52,161.48) -293.52,241.82 ; -257.33,241.82 cw(c-257.33,161.48) -200.53,218.29 ccw(c-257.33,161.48) -257.33,241.82 ; -257.33,241.82 ccw(c-257.33,322.15) -200.53,265.35 cw(c-257.33,322.15) -257.33,241.82
  BottomLayer w24: P2.5@-373.85,241.82 P2.5@-177,241.82 ; P2.5@-350.32,218.29 cw(c-293.52,161.48) -293.52,241.82 cw(c-293.52,322.15) P2.5@-350.32,265.35 ; P2.5@-200.53,218.29 ccw(c-257.33,161.48) -257.33,241.82 ccw(c-257.33,322.15) P2.5@-200.53,265.35
T-: F2.1 P2.4 | length 1790.2
  TopLayer w24: F2.1@-645.96,299.27 F2.1@-646.96,300.27 ; F2.1@-642.45,304.79 F2.1@-646.96,300.27 ; P2.4@-177,379.61 -457.39,379.61 -536.73,300.27 F2.1@-646.96,300.27 ; -623.65,300.27 cw(c-623.65,323.58) -640.13,307.1 ccw(c-623.65,323.58) -623.65,300.27 ; -623.65,300.27 ccw(c-623.65,276.97) -640.13,293.45 cw(c-623.65,276.97) -623.65,300.27 ; -454.18,379.61 cw(c-454.18,299.28) -397.38,356.08 ccw(c-454.18,299.28) -454.18,379.61 ; -454.18,379.61 ccw(c-454.18,459.95) -397.38,403.14 cw(c-454.18,459.95) -454.18,379.61 ; -293.52,379.61 cw(c-293.52,459.95) -350.32,403.14 ccw(c-293.52,459.95) -293.52,379.61 ; -293.52,379.61 ccw(c-293.52,299.28) -350.32,356.08 cw(c-293.52,299.28) -293.52,379.61 ; -257.33,379.61 cw(c-257.33,299.28) -200.53,356.08 ccw(c-257.33,299.28) -257.33,379.61 ; -257.33,379.61 ccw(c-257.33,459.95) -200.53,403.14 cw(c-257.33,459.95) -257.33,379.61
  BottomLayer w24: P2.4@-373.85,379.61 P2.4@-177,379.61 ; P2.4@-350.32,356.08 cw(c-293.52,299.28) -293.52,379.61 cw(c-293.52,459.95) P2.4@-350.32,403.14 ; P2.4@-200.53,356.08 ccw(c-257.33,299.28) -257.33,379.61 ccw(c-257.33,459.95) P2.4@-200.53,403.14
pads on no net: U1.2 U1.5 U1.6 U1.10 U1.11 U1.20 U1.21 U1.22 U1.25 U1.26 U1.27 U1.28 U1.29 U1.30 U1.31 U1.32 U1.33 U1.38 U1.39 U1.40 U1.41 U1.42 U1.43 U1.45 U1.46 U8.14 U11.7 U11.10

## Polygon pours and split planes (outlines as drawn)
GNDX on GND "VCC-No Net" (solid, remove dead copper): -493,0 -494,1023.62 -1338,1023.62 -1338,773 -1285.96,740 -1286,540 -1783,531.87 -1783,0 -491,0
AGND on GND "VCC-No Net" (solid, remove dead copper): -2262,0 -2263,1023.62 -1496,1023.62 -1496,640 -1835,640 -1835,272 -1912,272 -1912,0 -2262,0
GNDX on VCC "VCC-No Net" (solid, remove dead copper): -493,0 -494,1023.62 -1338,1023.62 -1338,773 -1285.96,740 -1286,540 -1783,531.87 -1783,0 -491,0
AGND on VCC "VCC-No Net" (solid, remove dead copper): -2262,0 -2263,1023.62 -1496,1023.62 -1496,640 -1835,640 -1835,272 -1912,272 -1912,0 -2262,0
GNDX on BottomLayer "VCC-No Net" (solid, remove dead copper): -493,1 -494,1024.62 -1338,1024.62 -1338,774 -1285.96,741 -1286,541 -1783,532.87 -1783,1 -491,1
AGND on BottomLayer "VCC-No Net" (solid, remove dead copper): -2262,0 -2263,1023.62 -1496,1023.62 -1496,640 -1835,640 -1835,272 -1912,272 -1912,0 -2262,0

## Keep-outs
KeepOutLayer:
  lines w12: -2755.91,0 0,0 0,1023.62 -2755.91,1023.62 -2755.91,0

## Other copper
TopLayer:
  rectangle net GNDX: -1788.96,222.87 -1719.96,243.87
  rectangle net GNDX: -1633.96,327.87 -1598.96,361.87
  rectangle net GNDX: -1671.96,265.87 -1629.96,348.87
  rectangle net GNDX: -1722.96,222.87 -1575.96,272.87
  rectangle net DVDD: -1648.96,370.87 -1571.96,392.87
  rectangle net DVDD: -1792.96,359.87 -1643.96,423.87
GND:
  rectangle net ISO+3V3: -2115,90 -2073,477
  rectangle net ISO+3V3: -2089.95,289 -1828,346
  rectangle net ISO+3V3: -1876,289 -1828,620
VCC:
  rectangle net DVDD: -1855,140 -1505,184
  rectangle net DVDD: -1721,140 -1684,367
  rectangle net DVDD: -1721,330 -1370,367
  rectangle net ISO+3V3: -1855,588 -1811,873
  rectangle net ISO+3V3: -1906,588 -1811,622
BottomLayer:
  rectangle net ISO+3V3: -1856,596 -1631.21,659.5
  rectangle net ISO+3V6: -1555,902 -1507,983
  rectangle net ISO+3V6: -1698,935 -1507,983
  rectangle net ISO+3V3: -1798,759 -1673,787
  rectangle net ISO+3V3: -1651,587 -1590,727
  rectangle net ISO+3V3: -1906,587 -1590,622
  pour cut-out: -869.96,341.87 -779.96,341.87 -749.56,372.27 -596.56,372.27 -595.96,372.87 -595.96,278.87 -755.96,278.87 -781.96,252.87 -869.96,252.87

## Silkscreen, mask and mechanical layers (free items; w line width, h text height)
TopOverlay:
  text "CubeIO-RTD" at -2716,961 h40
  text "V1.0" at -2715,905 h30
  text "A0" at -2494.95,817.03 h40 r270
  text "A0" at -2243,806 h40 r270
  text "V+" at -514,763.1 h40 r90
  text "V+" at -253.35,761.1 h40 r90
  text "B0" at -2494.95,684.03 h40 r270
  text "B0" at -2243,682 h40 r270
  text "G" at -514,642.1 h40 r90
  text "G" at -253.35,640.1 h40 r90
  text "C0/1" at -2494.95,578.03 h40 r270
  text "C0/1" at -2243,575 h40 r270
  text "SDI" at -514,473.1 h40 r90
  text "SDI" at -253.35,471.1 h40 r90
  text "B1" at -2494.95,399.03 h40 r270
  text "B1" at -2243,399 h40 r270
  text "T-" at -514,351.1 h40 r90
  text "T-" at -253.35,349.1 h40 r90
  text "A1" at -2494.95,265.03 h40 r270
  text "A1" at -2243,262 h40 r270
  text "T+" at -514,215.1 h40 r90
  text "T+" at -253.35,213.1 h40 r90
